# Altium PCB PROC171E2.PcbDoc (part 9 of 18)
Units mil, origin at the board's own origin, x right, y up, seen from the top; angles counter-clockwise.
Board outline 7700 x 2300 mil, 6 copper layers (Top Layer, GND 1, SIG 1, SIG 2, GND 2, Bottom Layer), stack 61.062 mil thick; 937 components, 687 nets, 11931 pads, 1719 vias.
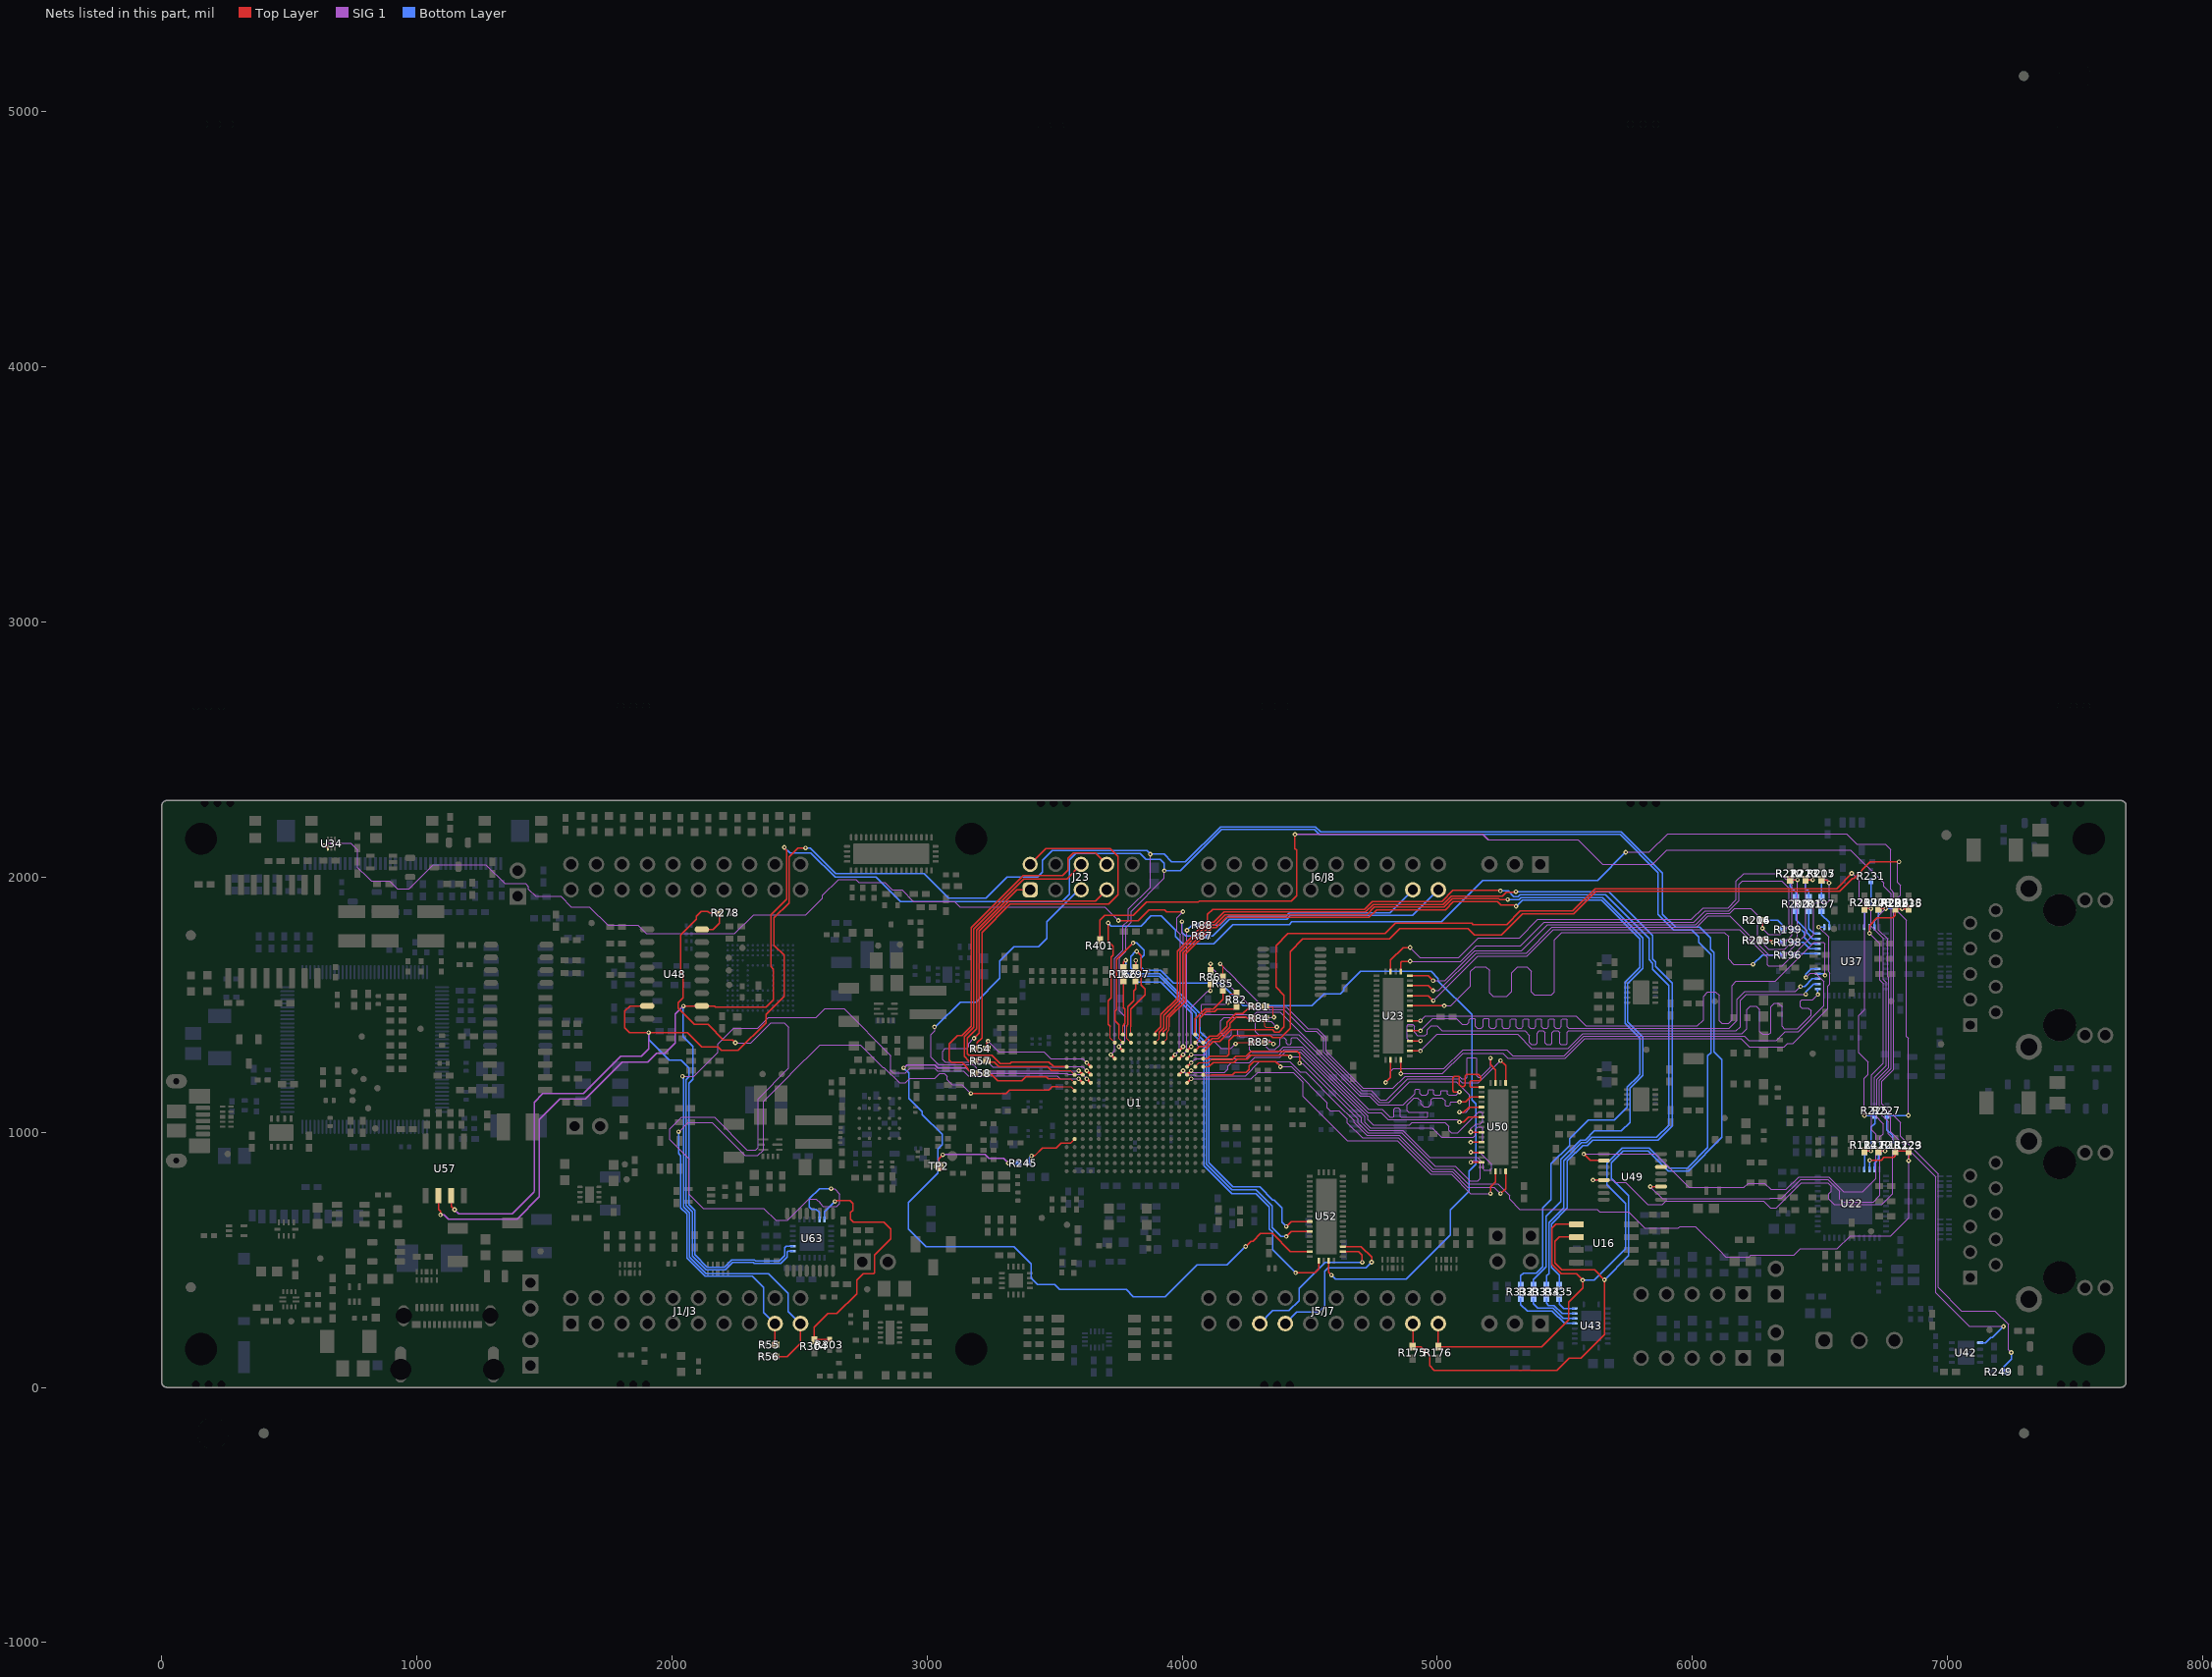
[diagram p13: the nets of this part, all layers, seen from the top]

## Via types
v1: diameter 18, hole 8, Top Layer to Bottom Layer, tented both sides, 1588 vias
v2: diameter 19.68, hole 7.87, Top Layer to Bottom Layer, tented both sides, 104 vias
v3: diameter 19.68, hole 7.87, Top Layer to Bottom Layer, 24 vias
v4: diameter 18, hole 8, Top Layer to Bottom Layer, 3 vias

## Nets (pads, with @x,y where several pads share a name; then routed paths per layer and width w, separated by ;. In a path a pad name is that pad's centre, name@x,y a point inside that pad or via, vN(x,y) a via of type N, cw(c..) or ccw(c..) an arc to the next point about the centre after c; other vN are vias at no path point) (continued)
AM263P_EQEP2_A: R332.1 U1.B13 | length 4022.5
  Top Layer w4: U1.B13@3925.09,1351.3 3940.83,1367.05 3940.83,1392.36 3949.66,1401.19 3949.66,1414.29
  Top Layer w5.3: 3949.66,1414.29 3949.66,1449.05 4013.1,1512.49 4013.1,1697.42 4117.13,1801.45 4132.6,1801.45 4173.13,1841.98 4732.22,1841.98 4762.54,1872.29 5031.26,1872.29 5063.8,1904.82 5236.7,1904.82 5250.28,1891.24 5300.05,1891.24 5305.32,1885.97 v1(5308.76,1885.97)
  Bottom Layer w5.3: v1(5308.76,1885.97) 5310.2,1885.97 5333.66,1909.42 5643.13,1909.42 5794.52,1758.03 5794.52,1646.1 5736.23,1587.8 5736.23,1427.78 5794.52,1369.49 5794.52,1226.91 5787.86,1220.25 5787.86,1219.97 5744.4,1176.5 5744.4,1097.83 5694.68,1048.11 5591.4,1048.11 5518.6,975.3 5518.6,948.55 5445.79,875.74 5445.79,735.68 5413.06,702.96 5413.06,473.21 5387.95,448.1 5338.15,448.1 5327.45,437.4 R332.1@5327.45,397.13
AM263P_EQEP2_A_R: R332.2 U43.6 | length 266.9
  Bottom Layer w5.3: R332.2@5327.45,349.89 5327.45,325.16 5352.6,300 5449.54,300 5499.07,250.47 U43.6@5538.7,250.47
AM263P_EQEP2_B: R333.1 U1.A13 | length 3975.7
  Top Layer w5.3: U1.A13@3925.09,1382.8 3926.32,1384.03 3926.32,1393.32 3938.37,1405.37 3938.37,1414.29 3938.37,1452.75 4002.5,1516.88 4002.5,1701.81 4112.74,1812.05 4128.21,1812.05 4168.74,1852.58 4723.68,1852.58 4754,1882.89 5026.87,1882.89 5059.41,1915.42 5241.09,1915.42 5244.49,1912.02 v1(5276.04,1912.02)
  Bottom Layer w5.3: v1(5276.04,1912.02) 5321.26,1912.02 5329.27,1920.02 5647.52,1920.02 5805.12,1762.42 5805.12,1641.71 5746.83,1583.41 5746.83,1432.17 5805.12,1373.88 5805.12,1222.24 5755,1172.11 5755,1038.76 5721.24,1005 5614.98,1005 5579.67,969.69 5561.6,969.69 5484.84,892.93 5484.84,727.99 5426.85,670 5426.85,472.01 5377.45,422.6 R333.1@5377.45,397.13
AM263P_EQEP2_B_R: R333.2 U43.7 | length 207.4
  Bottom Layer w5.3: R333.2@5377.45,349.89 5377.45,327.55 5394.4,310.6 5453.93,310.6 5494.38,270.15 U43.7@5538.7,270.15
AM263P_EQEP2_INDEX: R334.1 U1.A12 | length 4162.8
  Top Layer w5.3: U1.A12@3893.59,1382.8 3895.28,1384.49 3895.28,1392.88 3916.69,1414.29 3916.69,1461.05 3980.57,1524.93 3980.57,1709.86 4099.4,1828.69 4099.4,1853.45 4119.73,1873.78 4714.38,1873.78 4744.7,1904.09 5018.09,1904.09 5061.62,1947.62 5246.01,1947.62 v1(5247.69,1945.94)
  Bottom Layer w5.3: v1(5247.69,1945.94) 5277.72,1945.94 5300.15,1923.52 5317.77,1923.52 5324.87,1930.62 5659.38,1930.62 5830,1760 5830,1676.8 5844.52,1662.28 5844.52,1637.83 5907.5,1574.85 5907.5,1027.26 5860.24,980 5604.97,980 5584.06,959.09 5565.99,959.09 5495.44,888.54 5495.44,702.96 5437.45,644.97 5437.45,446.35 5428.06,436.97 R334.1@5428.06,397.13
AM263P_EQEP2_INDEX_R: R334.2 U43.8 | length 147.2
  Bottom Layer w5.3: R334.2@5428.06,349.89 5428.06,330 5436.86,321.2 5458.32,321.2 5489.68,289.84 U43.8@5538.7,289.84
AM263P_EQEP2_STROBE: R335.1 U1.B12 | length 4191.5
  Top Layer w4: U1.B12@3893.59,1351.3 3910,1367.71 3910,1385
  Top Layer w5.3: 3910,1385 3910,1391.99 3927.64,1409.63 3927.64,1414.29 3927.64,1457.01 3991.29,1520.66 3991.29,1705.59 4108.35,1822.65 4123.82,1822.65 4164.35,1863.18 4718.97,1863.18 4749.28,1893.49 5022.48,1893.49 5055.01,1926.02 5255.38,1926.02 5270.45,1941.1 5306.3,1941.1 v1(5308.24,1943.04)
  Bottom Layer w5.3: v1(5308.24,1943.04) 5671.96,1943.04 5843.5,1771.5 5843.5,1679.5 5855.48,1667.52 5855.48,1650.65 5921,1585.12 5921,1025.46 5865,969.46 5865,969.4 5609.36,969.4 5588.45,948.49 5570.38,948.49 5510,888.11 5510,702.53 5448.05,640.58 5448.05,469.67 5478.01,439.71 R335.1@5478.01,397.13
AM263P_EQEP2_STROBE_R: R335.2 U43.9 | length 91.1
  Bottom Layer w5.3: R335.2@5478.01,349.89 5478.01,326.51 5495,309.52 U43.9@5538.7,309.52
AM263P_EXT_REFCLK0: R245.2 TP2.1 | length 365.9
  Top Layer w5.3: TP2.1@3046.89,866.63 3046.89,896.68 v1(3061.63,911.42) ; v1(3318.54,878.86) v1@3320.15,880.47
  SIG 1 w5.3: v1(3061.63,911.42) 3062.87,912.67 3227.95,912.67 3243.11,897.5 3299.9,897.5 v1(3318.54,878.86)
  Bottom Layer w5.3: v1@3317.75,877.43 3356.3,877.43 R245.2@3358.26,879.39
AM263P_EXT_REFCLK0_R: R245.1 U1.P2 | length 230.8
  Top Layer w6: v1@3409.5,905.14 3412.6,908.24 3422.07,908.24 3451.8,937.97 3505.94,937.97 3515.64,947.66 3525.05,957.07 3563.22,957.07 3578.63,972.48 U1.P2@3578.63,973.35
  Bottom Layer w6: R245.1@3397.63,879.39 3399.6,881.36 3399.6,897.62 v1(3409.42,907.44)
AM263P_FSIRX1_CLK: J23.1 U1.E1 | length 1191.5
  Top Layer w5.3: J23.1@3404.17,1950 3351.31,1950 3193.88,1792.57 3193.88,1406.29 3157.31,1369.72 3157.31,1308.22 3164.4,1301.12 3254.65,1301.12 3287.22,1268.54 3324.45,1268.54 3330.96,1275.05 3477.96,1275.05 3496.2,1256.81 U1.E1@3547.13,1256.81
AM263P_FSIRX1_DATA0: J23.5 U1.F3 | length 1625.3
  Top Layer w10: v1(3594.38,1241.06) U1.F3@3610.13,1225.32
  SIG 1 w4: 3515.64,1241.06 v1(3594.38,1241.06)
  SIG 1 w4.75: v1(3028.75,1413.07) 3030.54,1411.28 3030.54,1397.07 3015.66,1382.19 3015.66,1293.34 3044.56,1264.44 3181.29,1264.44 3204.67,1241.06 3515.64,1241.06
  Bottom Layer w5.3: v1(3028.75,1413.07) 3032.18,1413.07 3036.81,1417.7 3037.49,1417.7 3130.32,1510.52 3192.55,1510.52 3285.17,1603.14 3285.17,1670.79 3340.49,1726.11 3436.11,1726.11 3470,1760 3470,1825.78 3587.73,1943.5 3597.67,1943.5 J23.5@3604.17,1950
AM263P_FSIRX1_DATA1: J23.7 U1.F4 | length 1786.4
  Top Layer w5.3: v1(3184.29,1368.47) 3204.48,1388.67 3204.48,1788.18 3321.8,1905.5 3659.67,1905.5 J23.7@3704.17,1950
  Top Layer w10: v1(3625.87,1241.06) U1.F4@3641.62,1225.32
  SIG 1 w4: 3538.18,1257.18 3604.95,1257.18 3605.32,1256.81 3610.13,1256.81 v1(3625.87,1241.06)
  SIG 1 w4.75: v1(3184.29,1368.47) 3183.67,1368.47 3163.43,1348.23 3163.43,1336.01 3155.32,1327.89 3071.12,1327.89 3060.93,1317.71 3060.93,1284.83 3071.27,1274.49 3238,1274.49 3257.49,1255 3515.64,1255 3536,1255 3538.18,1257.18
AM263P_FSITX1_CLK: J23.2 R54.1 | length 1595.6
  Top Layer w5.3: R54.1@3186.06,1327.26 3187.98,1327.26 3197.14,1336.42 3197.14,1351.52 3215.08,1369.46 3215.08,1783.79 3325.78,1894.49 3711.88,1894.49 3748.22,1930.82 3748.22,2080.28 3717,2111.5 3465.67,2111.5 J23.2@3404.17,2050
AM263P_FSITX1_CLK_R: R54.2 U1.E4 | length 476.6
  Top Layer w5.3: R54.2@3233.31,1327.26 3233.31,1347.96 3239.25,1353.91 v1(3239.25,1357.34)
  Top Layer w10: v1(3625.87,1272.56) U1.E4@3641.62,1256.81
  SIG 1 w4: 3516.64,1288.5 3609.93,1288.5 v1(3625.87,1272.56)
  SIG 1 w4.75: v1(3239.25,1357.34) 3281.1,1315.5 3458.5,1315.5 3485.5,1288.5 3516.64,1288.5
AM263P_FSITX1_DATA0: J23.6 R57.1 | length 1087.5
  Top Layer w5.3: R57.1@3186.06,1279.26 3164.45,1279.26 3146.71,1297 3146.71,1368.05 3146.71,1374.11 3183.28,1410.68 3183.28,1796.96 3379.82,1993.5 3547.67,1993.5 J23.6@3604.17,2050
AM263P_FSITX1_DATA0_R: R57.2 U1.F2 | length 369.5
  Top Layer w4: 3515.64,1242.94 3561.01,1242.94 U1.F2@3578.63,1225.32
  Top Layer w5.3: R57.2@3229.37,1274.26 3263.46,1274.26 3280.45,1257.28 3472.21,1257.28 3486.55,1242.94 3515.64,1242.94
AM263P_FSITX1_DATA1: J23.8 R58.1 | length 1385
  Top Layer w5.3: R58.1@3186.06,1231.26 3176.9,1240.42 3168.14,1240.42 3149.66,1258.9 3149.66,1261.26 3137.85,1273.07 3096.41,1273.07 3086.08,1283.4 3086.08,1345.64 3119.1,1378.65 3136.26,1378.65 3172.68,1415.07 3172.68,1801.35 3377.83,2006.5 3532,2006.5 3553,2027.5 3553,2074 3573,2094 3660.17,2094 J23.8@3704.17,2050
AM263P_FSITX1_DATA1_R: R58.2 U1.G2 | length 375.5
  Top Layer w4: 3515.64,1209.57 3562.88,1209.57 U1.G2@3578.63,1193.82
  Top Layer w5.3: R58.2@3229.37,1231.26 R58.2@3231.34,1229.29 ; R58.2@3233.31,1231.26 3239.8,1224.77 3253.9,1224.77 3276.19,1202.48 3372.36,1202.48 3386.66,1216.78 3468.18,1216.78 3475.39,1209.57 3515.64,1209.57
AM263P_I2C1_SCL: J5/J7.49 R175.1 U1.D7 U16.6 U48.15 U57.3 U63.19 | length 12800.5
  Top Layer w5.3: U57.3@1134.51,751.17 1134.51,709.57 v1(1147.56,696.52) ; U48.15@1902.72,1495 1836.12,1495 1815.31,1474.19 1815.31,1409.36 1834.1,1390.57 v1(1908.57,1390.57) 2061.37,1390.57 2116.89,1335.05 2180.06,1335.05 2194.47,1320.63 2259.71,1320.63 2368.82,1429.75 2368.82,1461.98 2439.32,1532.48 2439.32,1694.13 2400.25,1733.2 2400.25,1840.08 2459.36,1899.19 2459.36,2078.89 2494.29,2113.81 2523.18,2113.81 v1(2523.43,2114.06) ; J5/J7.49@4904.17,250 4904.17,160.51 R175.1@4903.31,159.65 4935.35,159.65 4970,125 4970,85 4988.58,66.42 5469.31,66.42 5517.89,115 5563.27,115 5655,206.73 v1(5655,421.38) 5616.38,460 5488.71,460 5460.6,488.11 5460.6,571.98 5477.76,589.14 U16.6@5545.51,589.14
  Top Layer w10: v1(3720.36,1304.06) U1.D7@3736.11,1288.31
  SIG 1 w4: v1(3720.36,1304.06) 3735.36,1319.06 3735.36,1414.29
  SIG 1 w4.75: 3735.36,1414.29 3735.36,1681.04 3768.42,1714.1 3768.42,1809.46 3788.96,1830 3788.96,1874.36 3875.05,1960.45 v1(3875.05,2090.05)
  SIG 1 w5.3: v1(1147.56,696.52) 1164.08,680 1374.68,680 1459.24,764.55 1459.65,771.37 1459.65,1117.7 1493.24,1151.3 1652.8,1151.3 1800.19,1298.68 1878.66,1298.68 1880.85,1298.68 1908.57,1326.4 v1(1908.57,1390.57)
  Bottom Layer w5.3: v1(1908.57,1390.57) 1908.57,1364.17 1990.18,1282.56 2036.19,1282.56 2066.43,1252.31 2066.43,1216.29 2055.87,1205.73 2055.87,712.1 2079.4,688.57 2079.4,515.53 2134.33,460.6 2210.09,460.6 2238.88,489.39 2319.16,489.39 2323.32,485.22 2426.48,485.22 2451.91,510.65 2451.91,529.97 2456.2,534.26 U63.19@2474.16,534.26 ; v1(2523.43,2114.06) 2525.03,2113.81 2542.42,2113.81 2641.86,2014.38 2988.14,2014.38 3085.39,1917.13 3231.37,1917.13 3314.22,1999.98 3433.73,1999.98 3452.63,2018.87 3452.63,2064.92 3491.48,2103.78 3861.33,2103.78 v1(3875.05,2090.05) 3928.67,2090.05 3958.8,2059.93 4012.43,2059.93 4149.82,2197.31 4522.96,2197.31 4542.87,2177.41 5720.79,2177.41 5882.72,2015.49 5882.72,1854.22 5933.8,1803.13 6029.61,1803.13 6070.97,1761.78 6070.97,1716.79 6083.8,1703.95 6083.8,1316.2 6115.71,1284.29 6115.71,979.72 5984.47,848.48 5905.04,848.48 5827.42,926.1 5728.23,926.1 5682.27,880.14 5682.27,819.31 5749.4,752.17 5749.4,515.78 v1(5655,421.38)
AM263P_I2C1_SDA: J5/J7.50 R176.1 U1.C8 U16.5 U48.2 U57.2 U63.20 | length 12243.2
  Top Layer w5.3: U57.2@1084.51,751.17 1084.51,698.33 1092.5,690.34 v1(1092.5,675.88) ; v1(2044.99,1494.52) 2045.03,1494.57 2116.85,1494.57 U48.2@2117.28,1495 2166.01,1495 2170.45,1490.56 2231.47,1490.56 2369.41,1490.56 2397.81,1518.96 2397.81,1638.97 2387.33,1649.45 2387.33,1851.36 2448.76,1912.79 2448.76,2104.87 2440.58,2113.06 v1(2440.58,2116.49) ; J5/J7.50@5004.17,250 R176.1@5004.17,159.65 5409.65,159.65 5515,265 5515,334.61 5570,389.61 v1(5570,420) 5545,445 5486.14,445 5450,481.14 5450,625 5464.14,639.14 U16.5@5545.51,639.14
  Top Layer w10: v1(3751.86,1335.55) U1.C8@3767.61,1319.8
  SIG 1 w4: v1(3751.86,1335.55) 3775.62,1359.32 3775.62,1425.57
  SIG 1 w4.75: 3775.62,1425.57 3775.62,1453.13 3753.75,1475 3753.75,1685.22 3778.47,1709.93 3778.47,1802.62 3800,1824.15 3800,1866.12 3930,1996.12 v1(3930,2024.75)
  SIG 1 w5.3: v1(1092.5,675.88) 1106.96,675.88 1123.49,659.35 1392.53,659.35 1480.31,747.13 1480.31,1050.57 1560.38,1130.65 1661.35,1130.65 1805.82,1275.11 1905,1275.11 1922.87,1292.98 1940.66,1310.45 1973.07,1310.45 2012.52,1349.9 2012.52,1462.69 2044.35,1494.52 v1(2044.99,1494.52)
  Bottom Layer w5.3: v1(2044.99,1494.52) 2043.96,1493.49 2043.96,1374.31 2082.6,1335.67 2082.6,1207.77 2066.47,1191.65 2066.47,716.49 2090,692.97 2090,519.92 2138.72,471.2 2205.7,471.2 2234.49,499.99 2323.55,499.99 2327.71,495.82 2420.18,495.82 2441.31,516.95 2441.31,547.87 2447.39,553.95 U63.20@2474.16,553.95 ; v1(2440.58,2116.49) 2460.98,2096.09 2462.53,2094.54 2545.02,2094.54 2546.57,2092.98 2639.6,1999.96 2800.02,1999.96 2895.45,1904.53 3528.85,1904.53 3558.06,1933.74 3558.06,2068.59 3582.65,2093.18 3835.03,2093.18 3857.68,2070.53 3913.88,2070.53 3930,2054.41 v1(3930,2024.75) 3993.14,2024.75 4155.1,2186.71 4518.31,2186.71 4538.21,2166.81 5716.4,2166.81 5865,2018.21 5865,1854.37 5926.84,1792.53 5998.02,1792.53 6025,1765.56 6025,1744.48 6073.2,1696.28 6073.2,1311.78 6060.48,1299.05 6060.48,939.48 5980.08,859.08 5909.44,859.08 5830.92,937.6 5724.74,937.6 5665.6,878.46 5665.6,793.26 5738.8,720.06 5738.8,543.9 5614.9,420 v1(5570,420)
AM263P_I2C3_SCL: J1/J3.9 R55.1 U1.H2 | length 3144.2
  Top Layer w4: 3515.64,1177.69 3563.27,1177.69 U1.H2@3578.63,1162.32
  Top Layer w5.3: R55.1@2404.17,170 J1/J3.9@2404.17,250 ; v1(3171.61,1152.13) 3191.21,1151.54 3309.84,1151.54 3322.76,1164.47 3477.91,1164.47 3491.13,1177.69 3515.64,1177.69
  SIG 1 w4.75: v1(2025.75,1002.09) 2028.24,1002.09 2063.81,1037.66 2157.87,1037.66 2286.49,909.03 2336.73,909.03 2358.9,931.2 2358.9,1120.98 2465.35,1227.43 2465.35,1227.82 2580.45,1342.92 2737.8,1342.92 2826.21,1254.51 2831.08,1254.51 2892.09,1193.5 2915.59,1193.5 2932.73,1210.64 3030.52,1210.64 3050.04,1230.16 3068.18,1230.16 3079.45,1218.89 3079.45,1205.56 3098.1,1186.91 3136.83,1186.91 v1(3171.61,1152.13)
  Bottom Layer w5.3: v1(2025.75,1002.09) 2025.75,917.01 2034.67,908.09 2034.67,703.32 2058.2,679.79 2058.2,506.75 2129.9,435.06 2315.8,435.06 2360,390.85 2360,294.17 J1/J3.9@2404.17,250
AM263P_I2C3_SDA: J1/J3.10 R56.1 U1.G3 | length 3368.7
  Top Layer w5.3: R56.1@2404.59,121 2452.33,121 2504.17,172.84 J1/J3.10@2504.17,250
  Top Layer w10: v1(3594.38,1209.57) U1.G3@3610.13,1193.82
  SIG 1 w4.75: v1(2041.52,1218.99) 2085.81,1218.99 2180.61,1313.79 2180.61,1345.43 2242.1,1406.92 2336.03,1406.92 2379.04,1449.94 2565.75,1449.94 2599.52,1483.71 2674.26,1483.71 2857.96,1300.01 2857.96,1241.85 2867.05,1232.76 2905.22,1232.76 2916.06,1232.74 2927.35,1244.03 2934.89,1251.58 3028.21,1251.58 3039.58,1240.21 3142.02,1240.21 3161.82,1220.41 3509.8,1220.41 3520.64,1209.57 v1(3594.38,1209.57)
  Bottom Layer w5.3: v1(2041.52,1218.99) 2043.95,1216.56 2043.95,1210.86 2045.27,1209.53 2045.27,707.71 2068.8,684.18 2068.8,511.14 2134.29,445.66 2379.01,445.66 2456.13,368.54 2456.13,298.04 J1/J3.10@2504.17,250
AM263P_ICSSM_MII0_COL: R207.1 R219.2 R231.2 U37.45 U49.11 | length 2477.8
  Top Layer w5.3: v1(5835,786.84) U49.11@5877.2,786.84 ; R207.1@6674.39,1876.46 v1(6700,1876.46)
  SIG 1 w4.75: v1(5835,786.84) 5881.84,740 6304.59,740 6305.65,741.06 6350.52,741.06 6424.46,815 6531.49,815 6578.11,768.37 6578.11,738.69 6589.88,726.92 6710,726.92 6735.75,752.67 6735.75,981.83 6748.64,994.71 6748.64,1033.27 6713.34,1068.57 6713.34,1215.64 6759.37,1261.68 6759.37,1322.67 6759.37,1586.7 6748.64,1597.44 6748.64,1759.67 6700,1808.31 v1(6700,1876.46)
  Bottom Layer w5.3: U37.45@6674.39,1803.9 6674.52,1804.03 6674.52,1876.32 R219.2@6674.39,1876.46 v1(6700,1876.46) R231.2@6700,1985
AM263P_ICSSM_MII0_CRS: U49.14
AM263P_ICSSM_MII0_RXCLK: R196.1 U23.32 | length 2179.7
  Top Layer w5.3: U23.32@4892.17,1495.87 v1(5026.97,1495.87)
  SIG 1 w4.75: v1(5026.97,1495.87) 5052.52,1495.87 5130,1573.35 5130,1630 5148.88,1648.88 5190,1648.88 5205,1633.88 5205,1547.01 5218.7,1533.31 5272.43,1533.31 5290.93,1551.81 5290.93,1625.68 5314.12,1648.88 5351.12,1648.88 5368.7,1631.3 5368.7,1550.78 5381.13,1538.35 5447.26,1538.35 5458.38,1549.47 5458.38,1753.76 5488.38,1783.75 6124.51,1783.75 6141.53,1766.73 6141.53,1678.12 6161.56,1658.09 v1(6237.52,1658.09)
  Bottom Layer w5.3: v1(6237.52,1658.09) 6274.47,1695.04 R196.1@6351.89,1695.04
AM263P_ICSSM_MII0_RXCLK_R: R196.2 U37.32 | length 94.1
  Bottom Layer w5.3: R196.2@6399.14,1695.04 6403.66,1699.57 U37.32@6491.32,1699.57
AM263P_ICSSM_MII0_RXD0: R198.1 R203.1 R215.2 U23.41 | length 2256.6
  Top Layer w5.3: U23.41@4817.36,1629.73 4817.36,1674.62 4866.61,1723.86 v1(4893.56,1723.86) ; R203.1@6275,1752.65 6307.35,1752.65 v1(6315,1745)
  SIG 1 w4.75: v1(4893.56,1723.86) 4932.42,1685 5083.11,1685 5160.35,1762.24 5322.96,1762.24 5394.72,1834 5996.48,1834 6042.48,1880 6140,1880 6172.02,1912.02 6172.02,1984.09 6202.08,2014.15 6344.69,2014.15 6390,1968.84 6390,1773.91 6361.09,1745 v1(6315,1745)
  Bottom Layer w5.3: R215.2@6274.92,1752.65 6305.55,1752.65 6313.2,1745 v1(6315,1745) v1(6315,1745) R198.1@6351.89,1745.04
AM263P_ICSSM_MII0_RXD0_R: R198.2 U37.33 | length 102.9
  Bottom Layer w5.3: R198.2@6399.14,1745.04 6434.21,1745.04 6460,1719.25 U37.33@6491.32,1719.25
AM263P_ICSSM_MII0_RXD1: R199.1 R204.1 R216.2 U23.39 | length 2182.3
  Top Layer w5.3: U23.39@4856.73,1629.73 4856.73,1664.99 4861.74,1670 v1(4893.56,1670) ; v1(6274.92,1798.96) 6275,1799.04 R204.1@6275,1830.96
  SIG 1 w4.75: v1(4893.56,1670) 5092.52,1670 5153.02,1730.5 5326.09,1730.5 5419.54,1823.95 6004.95,1823.95 6049.09,1868.09 6142.3,1868.09 6182.07,1907.86 6182.07,1970.68 6196.35,1984.95 6350.79,1984.95 6379.95,1955.79 6379.95,1809.66 6345.29,1775 6298.88,1775 v1(6274.92,1798.96)
  Bottom Layer w5.3: v1(6274.92,1798.96) 6275,1799.04 R216.2@6275,1830.96 6275.11,1830.85 6335,1830.85 6351.89,1813.96 R199.1@6351.89,1795.04
AM263P_ICSSM_MII0_RXD1_R: R199.2 U37.34 | length 126.8
  Bottom Layer w5.3: R199.2@6399.14,1795.04 6399.18,1795 6425.16,1795 6438.01,1782.15 6438.01,1762.74 6461.81,1738.94 U37.34@6491.32,1738.94
AM263P_ICSSM_MII0_RXD2: R200.1 R210.1 R222.2 U23.38 | length 2143.2
  Top Layer w5.3: U23.38@4892.17,1613.98 4964.13,1613.98 v1(4983.82,1594.29) ; R210.1@6383.01,1989.35 6411.65,1989.35 v1(6411.73,1989.27)
  SIG 1 w4.75: v1(4983.82,1594.29) 5031.03,1594.29 5148.36,1711.62 5329.69,1711.62 5431.97,1813.9 6013.95,1813.9 6058.09,1858.04 6146.47,1858.04 6165.12,1876.69 6228.31,1876.69 6255.67,1849.33 6255.67,1760.83 6298.88,1717.62 6362.62,1717.62 6411.73,1766.73 v1(6411.73,1989.27)
  Bottom Layer w5.3: R200.1@6406.28,1918.62 6406.28,1941.33 6383.01,1964.61 R222.2@6383.01,1989.35 6411.65,1989.35 v1(6411.73,1989.27)
AM263P_ICSSM_MII0_RXD2_R: R200.2 U37.35 | length 159.3
  Bottom Layer w5.3: R200.2@6406.28,1871.38 6406.28,1833.72 6448.61,1791.39 6448.61,1781.98 6471.97,1758.62 U37.35@6491.32,1758.62
AM263P_ICSSM_MII0_RXD3: R201.1 R211.1 R223.2 U23.36 | length 2185.7
  Top Layer w5.3: U23.36@4892.17,1574.61 4964.13,1574.61 v1(4983.82,1554.92) ; R211.1@6443.01,1989.35 v1(6471.73,1989.27) v1(6471.73,1989.27)
  SIG 1 w4.75: v1(4983.82,1554.92) 5005.87,1554.92 5152.52,1701.57 5331.99,1701.57 ccw(c5331.99,1706.32) 5333.16,1701.72 5335.42,1702.29 cw(c5336.59,1697.69) 5336.54,1702.44 5349.02,1702.53 5450.34,1803.85 6018.14,1803.85 6062.28,1847.99 6147.02,1847.99 6300.01,1695 6364.04,1695 6444.47,1775.43 6444.47,1999.47 6455,2010 6467.22,2010 6471.73,2005.49 v1(6471.73,1989.27)
  Bottom Layer w5.3: R201.1@6456.28,1918.62 6456.28,1943.72 6443.01,1956.99 R223.2@6443.01,1989.35 v1(6471.73,1989.27) v1(6471.73,1989.27)
AM263P_ICSSM_MII0_RXD3_R: R201.2 U37.36 | length 116.2
  Bottom Layer w5.3: R201.2@6456.28,1871.38 6456.28,1798.71 6476.68,1778.31 U37.36@6491.32,1778.31
AM263P_ICSSM_MII0_RXDV: R197.1 R205.1 R217.2 U23.34 | length 2228.3
  Top Layer w5.3: U23.34@4892.17,1535.24 4964.74,1535.24 v1(4984.43,1515.55) ; R205.1@6506.28,1989.43 6526.56,1989.43 6536.12,1979.87 v1(6536.12,1977.35)
  SIG 1 w4.75: v1(4984.43,1515.55) 5159.93,1691.06 5351.76,1691.06 5454.5,1793.8 6185.09,1793.8 6294.37,1684.51 6294.37,1656.36 6298.18,1652.56 6352.8,1652.56 6475.75,1775.51 6475.75,1890 6485.75,1900 6528.66,1900 6536.12,1907.46 v1(6536.12,1977.35)
  Bottom Layer w5.3: R197.1@6506.28,1918.62 R217.2@6506.28,1989.43 6526.56,1989.43 6536.12,1979.87 v1(6536.12,1977.35)
AM263P_ICSSM_MII0_RXDV_R: R197.2 U37.38 | length 80
  Bottom Layer w5.3: R197.2@6506.28,1871.38 6506.28,1852.66 6536.59,1822.35 U37.38@6536.59,1803.9
AM263P_ICSSM_MII0_RXER: R206.1 R218.2 R235.2 U37.46 U49.2 | length 2656.3
  Top Layer w5.3: v1(5574.59,914.8) 5600.18,889.2 U49.2@5652.8,889.2 ; v1(6694.59,1779.98) 6694.07,1780.5 6694.07,1810.03 6724.04,1840 6785,1840 6795,1850 6795,1874.79 R206.1@6796.28,1876.06 v1(6822.14,1876.06) R218.2@6848,1876.06
  SIG 1 w4.75: v1(5574.59,914.8) 5854.89,914.8 5986.39,783.3 6203.03,783.3 6219.76,800.03 6282.75,800.03 6307.03,775.75 6367.49,775.75 6416.79,825.05 6535.65,825.05 6593.6,767.1 6667.1,767.1 6719.25,819.25 6719.25,992.92 6703.29,1008.88 6703.29,1224.29 6749.32,1270.33 6749.32,1318.51 6749.32,1582.54 6735.75,1596.11 6735.75,1738.3 6694.59,1779.46 v1(6694.59,1779.98)
  Bottom Layer w5.3: U37.46@6694.07,1803.9 6694.33,1803.64 6694.33,1780.24 v1(6694.59,1779.98) ; v1(6822.14,1876.06) 6822.77,1876.69 R235.2@6848,1876.69
AM263P_ICSSM_MII0_RXLINK: R208.1 R220.2 R233.2 U37.47 U49.5 | length 2771.9
  Top Layer w5.3: v1(5610.59,812.43) U49.5@5652.8,812.43 ; R208.1@6729.39,1876.46 v1(6758,1876.46)
  SIG 1 w4.75: v1(5610.59,812.43) 5689.53,812.43 5697.98,803.98 5737.42,803.98 5824.99,716.41 5881.68,716.41 5895.21,729.95 6278.26,729.95 6305.65,702.56 6329.24,702.56 6427.29,800.6 6531.62,800.6 6544.25,787.97 6544.25,768.34 6534.22,758.31 6534.22,738.69 6556.04,716.87 6741.87,716.87 6785,760 6785,975.92 6766.98,993.94 6766.98,1041.66 6723.39,1085.25 6723.39,1208.39 6769.42,1254.42 6769.42,1326.83 6769.42,1605.75 6765,1610.18 6765,1757.52 6730,1792.52 6730,1848.46 v1(6758,1876.46)
  Bottom Layer w5.3: U37.47@6713.76,1803.9 6713.76,1829.37 6729.39,1845 R220.2@6729.39,1876.46 v1(6758,1876.46) 6794.76,1876.46 R233.2@6795,1876.69
AM263P_ICSSM_MII0_TXCLK: U23.19 U37.29 | length 2240.6
  Top Layer w5.3: v1(4797.68,1195.01) 4817.36,1214.69 U23.19@4817.36,1283.27
  SIG 1 w4.75: v1(4797.68,1195.01) 4816.93,1214.26 4816.93,1237.36 4828.77,1249.2 5026.48,1249.2 5100.59,1323.32 5271.68,1323.32 5295,1300 5497.08,1300 5574.45,1377.37 6203.73,1377.37 6221,1360.1 6329.33,1360.1 6364.23,1395 6414.93,1395 6516.08,1496.16 6516.08,1590.42 6483.53,1622.97 6461.5,1622.97 v1(6445,1606.47)
  Bottom Layer w5.3: v1(6445,1606.47) 6445,1619.87 6465.64,1640.51 U37.29@6491.32,1640.51
AM263P_ICSSM_MII0_TXD0: U23.29 U37.28 | length 2238.6
  Top Layer w5.3: U23.29@4892.17,1436.81 v1(4933.82,1436.81)
  SIG 1 w4.75: v1(4933.82,1436.81) 4953.26,1456.25 5543.75,1456.25 5582.43,1417.57 6020,1417.57 6043.31,1440.89 6043.31,1533.31 6060,1550 6090.94,1550 6104.93,1536.01 6104.93,1437.02 6114.98,1426.97 6141.97,1426.97 6155,1440 6155,1575.32 6172.02,1592.34 6325.23,1592.34 6477.9,1745 6514.23,1745 6520,1739.23 v1(6520,1615)
  Bottom Layer w5.3: U37.28@6491.32,1620.83 6514.17,1620.83 v1(6520,1615)
AM263P_ICSSM_MII0_TXD1: U23.27 U37.27 | length 2238.5
  Top Layer w5.3: U23.27@4892.17,1397.44 v1(4933.82,1397.44)
  SIG 1 w4.75: v1(4933.82,1397.44) 4982.58,1446.2 5073.64,1446.2 5097.17,1422.67 5116.6,1422.67 5125,1431.08 5125,1441.2 5130,1446.2 5145.03,1446.2 5150,1441.23 5150,1415.63 5157.93,1407.7 5171.95,1407.7 5180,1415.76 5180,1441.63 5184.57,1446.2 5200,1446.2 5204.29,1441.91 5204.29,1413.41 5210,1407.7 5225,1407.7 5231.71,1414.41 5231.71,1439.62 5237.09,1445 5250,1445 5255,1440 5255,1412.7 5260,1407.7 5280,1407.7 5286.71,1414.41 5286.71,1439.62 5292.09,1445 5305,1445 5310,1440 5310,1412.7 5315,1407.7 5330,1407.7 5336.71,1414.41 5336.71,1439.62 5342.09,1445 5355,1445 5360,1440 5360,1412.7 5365,1407.7 5380,1407.7 5386.71,1414.41 5386.71,1439.62 5392.09,1445 5405,1445 5410,1440 5410,1412.7 5415,1407.7 5430,1407.7 5436.71,1414.41 5436.71,1439.62 5442.09,1445 5455,1445 5460,1440 5460,1412.7 5465,1407.7 5480,1407.7 5486.71,1414.41 5486.71,1439.62 5492.09,1445 5505,1445 5510,1440 5510,1412.7 5515.18,1407.52 6145,1407.52 6175,1437.52 6175,1520.85 6206.45,1552.3 6404.57,1552.3 v1(6423.51,1571.24)
  Bottom Layer w5.3: v1(6423.51,1571.24) 6439.75,1571.24 6469.65,1601.14 U37.27@6491.32,1601.14
AM263P_ICSSM_MII0_TXD2: U23.25 U37.26 | length 2238.4
  Top Layer w5.3: U23.25@4892.17,1358.07 v1(4933.82,1358.07)
  SIG 1 w4.75: v1(4933.82,1358.07) 4890.94,1358.07 4881.77,1367.25 4881.77,1417.84 4886.61,1422.67 4903.59,1422.67 4910,1416.26 4910,1391.44 4923.24,1378.19 4952.19,1378.19 4961,1387 4961,1401.85 4975.85,1416.69 4999.73,1416.69 5018.95,1397.47 5343.6,1397.47 5361.5,1379.57 5361.5,1351.08 5369.16,1343.42 5385.21,1343.42 5391.78,1349.99 5391.78,1389.25 5400,1397.47 5415,1397.47 5422.49,1389.98 5422.49,1350.49 5428.06,1344.92 5445.48,1344.92 5450,1349.43 5450,1390 5457.47,1397.47 5472.53,1397.47 5480,1390 5480,1348.38 5484.96,1343.42 5506.27,1343.42 5510,1347.15 5510,1392.47 5515,1397.47 6171.47,1397.47 6187.84,1413.84 6187.84,1517.25 6211.44,1540.85 v1(6444.47,1540.85)
  Bottom Layer w5.3: v1(6444.47,1540.85) 6444.47,1550.71 6475.21,1581.46 U37.26@6491.32,1581.46
AM263P_ICSSM_MII0_TXD3: U23.23 U37.25 | length 2240.1
  Top Layer w5.3: U23.23@4892.17,1318.7 v1(4933.82,1318.7)
  SIG 1 w4.75: v1(4933.82,1318.7) 4999.46,1384.35 5314.02,1384.35 5369,1329.37 5512.23,1329.37 5570.29,1387.42 6195,1387.42 6213.36,1405.78 6213.36,1481.49 6226.22,1494.36 6250.2,1494.36 6263.7,1480.85 6263.7,1394.54 6274.46,1383.78 6299.87,1383.78 6307.32,1391.23 6307.32,1492.72 6320.6,1506 6336.86,1506 6351.36,1491.5 6351.36,1415.04 6360.4,1406 6411.71,1406 6465,1459.29 6465,1476.21 6454.84,1486.37 6428.68,1486.37 6422.79,1492.26 6422.79,1514.18 6428.61,1520 6472.17,1520 v1(6492.17,1540)
  Bottom Layer w5.3: U37.25@6491.32,1561.77 6491.32,1540.85 v1(6492.17,1540)
AM263P_ICSSM_MII0_TXEN: U23.21 U37.37 | length 2239.7
  Top Layer w5.3: U23.21@4856.73,1283.27 4856.73,1230.33 v1(4857.11,1229.96)
  SIG 1 w4.75: v1(4857.11,1229.96) 4857.15,1230 5021.49,1230 5101.48,1309.99 5257.38,1309.99 5277.42,1289.95 5501.24,1289.95 5578.61,1367.32 6190.85,1367.32 6223.21,1334.96 6360.2,1334.96 6373.06,1347.82 6395.09,1347.82 6531.62,1484.35 6531.62,1572.37 6539.25,1580 6539.25,1622.97 6534.22,1628 6534.22,1764.68 v1(6495,1803.9)
  Bottom Layer w5.3: v1(6495,1803.9) U37.37@6516.91,1803.9
AM263P_ICSSM_MII1_COL: R112.1 R124.2 R225.2 U1.C18 U22.45 | length 4383.9
  Top Layer w5.3: U1.C18@4082.57,1319.8 4086.6,1319.8 4122.5,1355.7 4146.29,1355.7 4191.74,1401.15 4354.6,1401.15 4362.85,1392.9 4379.03,1392.9 4399.89,1413.76 4399.89,1537.42 4367.66,1569.64 4367.66,1731.16 4414.88,1778.38 4794.45,1778.38 4835.37,1819.29 5135.52,1819.29 5140.61,1814.2 5272.38,1814.2 5325.08,1866.9 5530.18,1866.9 5618.28,1955 6564.92,1955 v1(6624.77,2014.85) ; R112.1@6674.39,926.46 v1(6700,926.46)
  SIG 1 w4.75: v1(6624.77,2014.85) 6655.14,1984.49 6655.14,1912.02 6675.34,1891.82 6675.34,1481.02 6652.14,1457.82 6652.14,1311.31 6689.32,1274.13 6689.32,1225.94 6674.39,1211 v1(6674.39,1065)
  Bottom Layer w5.3: U22.45@6674.39,853.9 6674.52,854.03 6674.52,926.32 R124.2@6674.39,926.46 v1(6700,926.46) 6700,1020 6715,1035 R225.2@6715,1064.94 6674.45,1064.94 v1(6674.39,1065)
AM263P_ICSSM_MII1_RXCLK: U1.E16 U50.31 | length 1530.3
  Top Layer w5.3: v1(5131.16,1000.35) U50.31@5173.43,1000.35
  Top Layer w10: U1.E16@4019.57,1256.81 v1(4035.32,1272.56)
  SIG 1 w4: v1(4035.32,1272.56) 4051.82,1289.06 4114.06,1289.06
  SIG 1 w4.75: 4114.06,1289.06 4250.66,1289.06 4265.61,1304 4379.88,1304 4400.29,1324.4 4466.88,1324.4 4728.5,1062.79 4728.5,1048.88 4749.39,1027.99 4891.44,1027.99 4901.66,1038.21 5029.44,1038.21 5045,1022.66 5045,1007.89 5055.05,997.84 5080.12,997.84 5163.56,1081.29 5170.68,1081.29 5177.73,1074.24 5177.73,1041.58 5168.72,1032.57 5150.46,1032.57 5131.16,1013.27 v1(5131.16,1000.35)
AM263P_ICSSM_MII1_RXD0: U1.F18 U50.42 | length 1527.9
  Top Layer w4: U1.F18@4082.57,1225.32 4113.77,1225.32 4114.06,1225.03
  Top Layer w5.3: 4114.06,1225.03 4115.16,1223.93 4196.2,1223.93 4206.8,1234.53 4250.64,1234.53 4262.08,1245.97 4262.08,1260.07 4279.71,1277.7 4366.78,1277.7 4384.99,1259.48 v1(4384.99,1256.82) ; v1(5248.23,759.55) 5267.91,779.23 U50.42@5267.91,846.81
  SIG 1 w4.75: v1(4384.99,1256.82) 4427.22,1256.82 4569.17,1114.87 4569.17,1096.28 4580.55,1084.9 4614.61,1084.9 4647.95,1051.56 4647.95,1036.76 4706.97,977.74 4847.67,977.74 4979.44,845.97 5058.54,845.97 5119.51,785 5222.77,785 v1(5248.23,759.55)
AM263P_ICSSM_MII1_RXD1: U1.G16 U50.40 | length 1530.8
  Top Layer w5.3: v1(5208.86,759.55) 5208.86,785.31 5228.54,805 U50.40@5228.54,846.81
  Top Layer w10: U1.G16@4019.57,1193.82 v1(4035.32,1209.57)
  SIG 1 w4.75: v1(4035.32,1209.57) 4270.86,1209.57 4296.38,1235.08 4434.74,1235.08 4474.51,1195.31 4474.51,1140.59 4647.41,967.69 4843.5,967.69 4975.28,835.92 5054.38,835.92 5130.76,759.55 v1(5208.86,759.55)
AM263P_ICSSM_MII1_RXD2: U1.E17 U50.37 | length 1529.3
  Top Layer w4: U1.E17@4051.07,1256.81 4066.82,1272.56 4101.95,1272.56 4113.62,1284.23 4114.06,1284.23
  Top Layer w5.3: 4114.06,1284.23 4197.31,1284.23 4210.63,1297.55 4250.64,1297.55 4270.36,1317.28 4450.47,1317.28 4460,1307.75 v1(4460,1271.09) ; v1(5131.77,882.24) U50.37@5173.43,882.24
  SIG 1 w4.75: v1(4460,1271.09) 4461.55,1269.54 4471.38,1269.54 4690.23,1050.69 4690.23,1036.35 4728.73,997.84 4860.42,997.84 4990.73,867.53 5070.26,867.53 5127.8,810 5158.56,810 5167.94,819.38 5167.94,876.31 5154.35,889.89 5141.18,889.89 5133.53,882.24 v1(5131.77,882.24)
AM263P_ICSSM_MII1_RXD3: U1.E18 U50.35 | length 1525.8
  Top Layer w4: U1.E18@4082.57,1256.81 4104.96,1256.81
  Top Layer w5.3: 4104.96,1256.81 4121.72,1273.58 4202.45,1273.58 4215.82,1286.95 4255.03,1286.95 4270.57,1302.49 4414.23,1302.49 4421.61,1295.1 v1(4423.69,1295.1) ; v1(5131.77,921.61) U50.35@5173.43,921.61
  SIG 1 w4.75: v1(4423.69,1295.1) 4463.21,1295.1 4702.13,1056.19 4702.13,1038.66 4732.9,1007.89 4864.58,1007.89 4970.98,901.49 5157.7,901.49 5180,879.19 5180,854.78 5182.78,851.99 5211.08,851.99 5213.86,854.78 5213.86,875 5167.25,921.61 v1(5131.77,921.61)
AM263P_ICSSM_MII1_RXDV: U1.F16 U50.33 | length 1526.7
  Top Layer w5.3: v1(5131.16,960.98) U50.33@5173.43,960.98
  Top Layer w10: U1.F16@4019.57,1225.32 v1(4035.32,1241.06)
  SIG 1 w4.75: v1(4035.32,1241.06) 4041.58,1234.81 4166.03,1234.81 4180,1248.78 4180,1259.38 4193.93,1273.3 4265,1273.3 4285.64,1293.95 4384.05,1293.95 4404.45,1314.35 4462.72,1314.35 4716.57,1060.5 4716.57,1038.43 4737.06,1017.94 4979.18,1017.94 5016.02,981.1 5142.47,981.1 5150.41,989.04 5150.41,1010.7 5159.71,1020 5173.32,1020 5177.73,1015.59 5177.73,969.09 5169.62,960.98 v1(5131.16,960.98)
AM263P_ICSSM_MII1_RXER: R111.1 R123.2 R229.2 U1.F15 U22.46 | length 3812.4
  Top Layer w5.3: v1(6695,890) 6740,890 6751.09,901.09 6789.71,901.09 6795,906.38 6795,924.79 R111.1@6796.28,926.06 R123.2@6848,926.06 v1(6848,888.56)
  Top Layer w10: U1.F15@3988.08,1225.32 v1(4003.83,1241.06)
  SIG 1 w4.75: v1(4003.83,1241.06) 4019.95,1224.94 4048.81,1224.94 4051.93,1221.82 4248.36,1221.82 4302.6,1276.07 4415.5,1276.07 4415.71,1275.85 4422.39,1275.85 4461.67,1236.58 4483.31,1236.58 4607.66,1112.23 ; 4607.66,1112.2 4674.65,1045.21 4674.65,1037.26 4724.12,987.79 4851.83,987.79 4983.6,856.02 5062.71,856.02 5120.89,797.83 5237.16,797.83 5283.33,751.67 5283.33,738.42 5323.62,698.12 5627.08,698.12 5636.41,688.8 5692.35,688.8 5692.41,688.86 5708.36,688.86 5708.42,688.8 5748.94,688.8 5813.88,623.85 5944.6,623.85 5951.6,630.85 6011.1,630.85 6104.93,537.03 6131.2,510.75 6222.36,510.75 6229.94,518.33 6398.53,518.33 6423.2,543 6568.25,543 6619.77,594.53 6777.57,594.53 6848,664.96 v1(6848,888.56)
  Bottom Layer w5.3: U22.46@6694.07,853.9 6694.07,889.07 v1(6695,890) ; R229.2@6846.59,927.98 6846.59,889.97 v1(6848,888.56)
AM263P_ICSSM_MII1_RXLINK: R110.1 R122.2 R227.2 U1.D18 U22.47 | length 4682.2
  Top Layer w5.3: U1.D18@4082.57,1288.31 4100.01,1288.31 4109.25,1297.55 4114.06,1297.55 4175.56,1297.55 4184.2,1306.2 4184.2,1360.45 4202.39,1378.64 4347.13,1378.64 4354.07,1371.7 4387.81,1371.7 4423.28,1407.16 4423.28,1708.76 4471.69,1757.18 4813.15,1757.18 4854.07,1798.09 5119.88,1798.09 5145.13,1772.84 5250.58,1772.84 5334.04,1856.3 5534.57,1856.3 5622.67,1944.4 6576.79,1944.4 6627.71,1995.33 6632.86,1995.33 6697.54,2060 v1(6810,2060) ; R110.1@6729.39,926.46 v1(6755,926.46)
  SIG 1 w4.75: v1(6810,2060) 6803.55,2053.55 6803.55,1979.56 6815.53,1967.58 6815.53,1930 6802.89,1917.36 6802.89,1868.09 6839.95,1831.03 6839.95,1375.84 6846.59,1369.2 v1(6846.59,1065.8)
  Bottom Layer w5.3: U22.47@6713.76,853.9 6713.76,879.37 6729.39,895 R122.2@6729.39,926.46 v1(6755,926.46) 6785,956.46 6785,987.75 6762.73,1010.01 R227.2@6762.73,1065.31 6846.11,1065.31 v1(6846.59,1065.8)
AM263P_ICSSM_MII1_TXCLK: R86.1 U50.18 | length 1596.1
  Top Layer w5.3: R86.1@4111,1632.17 v1(4111,1660.23) ; v1(5248.23,1280.53) 5267.91,1260.84 U50.18@5267.91,1193.26
  SIG 1 w4.75: v1(4111,1660.23) 4111.4,1659.82 4111.4,1648.85 4279.65,1480.6 4399.37,1480.6 4484.34,1395.64 4525.74,1395.64 4555,1366.38 4555,1312.77 4705.46,1162.31 4741.59,1162.31 4777.03,1126.87 4800.47,1126.87 4883.5,1209.9 5081.16,1209.9 5096.79,1194.27 5161.97,1194.27 v1(5248.23,1280.53)
AM263P_ICSSM_MII1_TXCLK_R: R86.2 U1.C16 | length 308.1
  Top Layer w4: v1(4110.55,1554.46) 4110.55,1583.95 R86.2@4110.9,1584.29
  Top Layer w10: U1.C16@4019.57,1319.8 v1(4035.32,1335.55)
  SIG 1 w4: v1(4035.32,1335.55) 4035.32,1414.29
  SIG 1 w4.75: 4035.32,1414.29 4035.32,1489.06 4098.14,1551.88 4104.38,1551.88 4106.97,1554.46 v1(4110.55,1554.46)
AM263P_ICSSM_MII1_TXD0: R81.1 U50.28 | length 1656.7
  Top Layer w4.75: R81.1@4330.08,1492.68 4354.68,1492.68 4357.46,1489.9 4357.46,1453.29 v1(4360,1450.76)
  Top Layer w5.3: v1(5086.77,1039.72) 5087.15,1040.1 5103.84,1040.1 5123.15,1059.41 U50.28@5173.43,1059.41
  SIG 1 w4.75: v1(4360,1450.76) 4164.17,1450.76 4150.83,1437.42 4150.83,1389.74 4166.32,1374.25 4185.04,1374.25 4193.93,1383.14 4193.93,1400.93 4197.49,1404.49 4214.45,1404.49 4217.23,1401.71 4217.23,1381.95 4224.93,1374.25 4288.08,1374.25 4297.32,1365 4297.32,1346.11 4294.33,1343.12 4267.78,1343.12 4265,1340.34 4265,1322.85 4273.8,1314.05 4375.72,1314.05 4396.13,1334.45 4471.04,1334.45 4728.5,1077 4779.38,1077 4807.3,1049.09 5077.41,1049.09 v1(5086.77,1039.72)
AM263P_ICSSM_MII1_TXD0_R: R81.2 U1.B18 | length 267.7
  Top Layer w5.3: U1.B18@4082.57,1351.3 4108.55,1377.29 4137.9,1377.29 4176.16,1415.55 4176.16,1430.7 4209.92,1464.46 4237.54,1464.46 4257.59,1484.51 4274.67,1484.51 R81.2@4282.84,1492.68
AM263P_ICSSM_MII1_TXD1: R82.1 U50.26 | length 1655.1
  Top Layer w4.75: v1(4179.19,1508.25) 4179.19,1531.6 4190.82,1543.23 R82.1@4212.87,1543.23
  Top Layer w5.3: v1(5086.77,1079.09) 5104.16,1079.09 5123.85,1098.78 U50.26@5173.43,1098.78
  SIG 1 w4.75: v1(4179.19,1508.25) 4176.84,1508.25 4169.78,1501.19 4077.69,1501.19 4074.9,1498.41 4074.9,1465.84 4079.64,1461.1 4124.01,1461.1 4124.14,1460.97 4283.08,1460.97 4292.39,1470.28 4383.28,1470.28 4701.77,1151.79 4737.89,1151.79 4772.86,1116.82 4810,1116.82 4890.95,1197.77 5074.44,1197.77 5127.21,1145.01 5127.21,1094.1 5112.19,1079.09 v1(5086.77,1079.09)
AM263P_ICSSM_MII1_TXD1_R: R82.2 U1.B17 | length 269.2
  Top Layer w4: U1.B17@4051.07,1351.3 4068.69,1368.92 4068.69,1414.29
  Top Layer w5.3: 4068.69,1414.29 4068.69,1446.09 4095.14,1472.55 4127.82,1472.55 4138.16,1482.89 4203.71,1482.89 4212.87,1492.05 R82.2@4212.87,1495.98
AM263P_ICSSM_MII1_TXD2: R83.1 U50.24 | length 1511
  Top Layer w4.75: R83.1@4324.87,1353.13 4348.14,1353.13 4354.85,1346.42 v1@4357.02,1346.42
  Top Layer w5.3: v1(5086.77,1118.46) 5110.31,1118.46 5130,1138.15 U50.24@5173.43,1138.15
  SIG 1 w4.75: v1(4357.55,1346.15) 4343.27,1360.42 4335.8,1360.42 4325.24,1349.87 4325.24,1337.5 4338.64,1324.1 4364.69,1324.1 4383.16,1342.57 4383.16,1365.86 4387.84,1370.54 4399.37,1370.54 4407.78,1362.14 4407.78,1350 4413.15,1344.63 4423.05,1344.63 4428.41,1349.98 4428.41,1367.11 4431.84,1370.54 4449.17,1370.54 4729.02,1090.69 4783.55,1090.69 4815.1,1059.14 4826.97,1059.14 4829.75,1061.92 4829.75,1090.18 4836.29,1096.72 4847.67,1096.72 4855.63,1088.76 4855.63,1062.14 4858.63,1059.14 4960.56,1059.14 4963.34,1061.92 4963.34,1075.99 4960.56,1078.78 4888.64,1078.78 4882.39,1085.02 4882.39,1108.3 4909.09,1135 4923.24,1135 4935.59,1122.65 4935.59,1111.61 4947.57,1099.63 4966,1099.63 4976.85,1110.49 4976.85,1127.67 4984.19,1135 5019.14,1135 5031.47,1122.67 5031.47,1105.62 5034.26,1102.84 5045.64,1102.84 5050.6,1107.8 5050.6,1115.68 5053.38,1118.46 v1(5086.77,1118.46)
AM263P_ICSSM_MII1_TXD2_R: R83.2 U1.D16 | length 396.3
  Top Layer w4.75: v1@4206.88,1351.06 4208.96,1348.98 4215.3,1348.98 4217.39,1351.06 4275.55,1351.06 R83.2@4277.62,1353.13
  Top Layer w10: U1.D16@4019.57,1288.31 v1(4035.32,1304.06)
  SIG 1 w4.75: v1(4035.32,1304.06) 4089.18,1304.06 4093.43,1308.3 4093.43,1330.34 4087,1336.78 4063.44,1336.78 4059.87,1340.35 4059.87,1351.72 4064.35,1356.2 4125.54,1356.2 4152.86,1328.88 4191.63,1328.88 v1(4209.18,1346.44)
AM263P_ICSSM_MII1_TXD3: R84.1 U50.22 | length 1628.6
  Top Layer w4.75: R84.1@4324.87,1445.88 4324.87,1415.2 4327.65,1412.42 v1(4370.94,1412.42)
  Top Layer w5.3: v1(5086.77,1157.83) 5065.63,1157.83 5060,1163.46 5060,1212.97 5066.68,1219.65 5083.67,1219.65 5086.77,1216.55 5086.77,1186.62 5094.7,1178.69 5102.75,1178.69 5108.69,1184.63 5108.69,1219.52 5115,1225.83 5160.62,1225.83 5169.97,1216.48 5169.97,1205.57 5166.86,1202.46 5131.69,1202.46 5128.59,1199.36 5128.59,1180.62 5131.69,1177.52 U50.22@5173.43,1177.52
  SIG 1 w4.75: v1(4370.94,1412.42) 4349.29,1434.07 4293.37,1434.07 4288.21,1428.91 4288.21,1393.36 4299.62,1381.95 4457.4,1381.95 4697.6,1141.74 4733.73,1141.74 4768.7,1106.77 4866.65,1106.77 4912.39,1152.51 4912.39,1165.47 4916.79,1169.87 4928.94,1169.87 4932.42,1166.39 4932.42,1152.63 4938.17,1146.88 4956.11,1146.88 4963.82,1154.59 4963.82,1163.61 4966.6,1166.39 4982.22,1166.39 4985,1163.61 4985,1150.05 4990,1145.05 5010,1145.05 5014.57,1149.62 5014.57,1160.66 5017.36,1163.44 5037.22,1163.44 5040,1160.66 5040,1150.05 5045,1145.05 5073.99,1145.05 v1(5086.77,1157.83)
AM263P_ICSSM_MII1_TXD3_R: R84.2 U1.C17 | length 293.3
  Top Layer w5.3: U1.C17@4051.07,1319.8 4068.04,1336.78 4088.58,1336.78 4118.11,1366.3 4141.9,1366.3 4186.76,1411.16 4186.76,1426.31 4213.15,1452.7 4249.44,1452.7 4256.26,1445.88 R84.2@4277.62,1445.88
AM263P_ICSSM_MII1_TXEN: R85.1 U50.20 | length 1683.4
  Top Layer w4.75: v1(4149,1660.23) 4159.49,1649.74 R85.1@4159.49,1607.02
  Top Layer w5.3: v1(5208.86,1290.74) 5208.86,1264.69 5228.54,1245 U50.20@5228.54,1193.26
  SIG 1 w4.75: v1(4149,1660.23) 4209.95,1599.28 4209.95,1598.74 4318.04,1490.65 4407.8,1490.65 4492.77,1405.69 4529.9,1405.69 4565.05,1370.54 4565.05,1316.93 4709.62,1172.36 4826.74,1172.36 4874.33,1219.95 5085.33,1219.95 5095.23,1210.05 5111.68,1210.05 5116.23,1214.6 5116.23,1289.96 5119.01,1292.74 5152.1,1292.74 5154.88,1289.96 5154.88,1221.62 5161.5,1215 5168.49,1215 5208.86,1255.37 v1(5208.86,1290.74)
AM263P_ICSSM_MII1_TXEN_R: R85.2 U1.A17 | length 240.8
  Top Layer w5.3: U1.A17@4051.07,1382.8 4051.07,1414.29 4051.07,1444.18 4090.03,1483.15 4122.33,1483.15 4159.49,1520.3 R85.2@4159.49,1559.77
AM263P_IEP0_EDC_SYNC_OUT0: J6/J8.72 R88.1 | length 862.6
  Bottom Layer w5.3: R88.1@4098.66,1812.24 4147.24,1812.24 4181.13,1846.13 4406.25,1846.13 4420.63,1860.51 4814.68,1860.51 J6/J8.72@4904.17,1950
AM263P_IEP0_EDC_SYNC_OUT0_R: R88.2 U1.D15 | length 565.1
  Top Layer w10: U1.D15@3988.08,1288.31 v1(4003.83,1304.06)
  SIG 1 w4: v1(4003.83,1304.06) 4018.83,1319.06 4018.83,1414.29
  SIG 1 w4.75: 4018.83,1414.29 v1(4018.83,1791.62)
  Bottom Layer w5.3: v1(4018.83,1791.62) 4039.45,1812.24 R88.2@4059.29,1812.24
AM263P_IEP0_EDIO_DATA_IN_OUT31: J6/J8.71 R87.1 | length 980.4
  Bottom Layer w5.3: R87.1@4098.66,1769.24 4119.24,1769.24 4185.53,1835.53 4410.64,1835.53 4424.63,1849.52 4903.7,1849.52 J6/J8.71@5004.17,1950
AM263P_IEP0_EDIO_DATA_IN_OUT31_R: R87.2 U1.C15 | length 621.7
  Top Layer w10: U1.C15@3988.08,1319.8 v1(4003.83,1335.55)
  SIG 1 w4: v1(4003.83,1335.55) 4003.83,1414.29
  SIG 1 w4.75: v1(3999.3,1825.38) 3999.58,1825.11 3999.58,1783.65 4003.83,1779.4 4003.83,1414.29
  Bottom Layer w5.3: v1(3999.3,1825.38) 3999.3,1783.54 4013.6,1769.24 R87.2@4059.29,1769.24
AM263P_INT1_PB_GPIO123: U1.D14 U34.4 | length 4450
  Top Layer w5.3: v1(635.66,2123.71) 643.9,2115.47 U34.4@651.22,2115.47 ; v1(3750,1830) 3827.92,1830 3869.54,1871.62 3930.98,1871.62 3938.17,1864.43 v1(4003.05,1864.43)
  Top Layer w10: U1.D14@3956.58,1288.31 v1(3972.33,1304.06)
  SIG 1 w4: v1(3972.33,1304.06) 3988.83,1320.55 3988.83,1414.29
  SIG 1 w4.75: v1(635.66,2123.71) 645.95,2134 741.21,2134 768.33,2106.89 768.33,2036.68 782,2023 ; 782.08,2023.08 793.15,2012.84 821.4,1984.59 893.41,1984.59 923,1955 970,1955 1063.74,2048.74 1270.43,2048.74 1344.17,1975 1424.99,1975 1438.27,1961.73 1438.27,1952.73 1466.13,1924.87 1563.87,1924.87 1605.23,1883.5 1676.77,1883.5 1748.63,1811.63 1867.13,1811.63 1900,1778.77 2246.64,1778.77 2319.87,1851.99 2525.34,1851.99 2538.28,1864.94 2590.04,1916.69 2590.04,1920.49 cw(c2594.79,1920.49) 2590.04,1920.68 2590.05,1920.87 2590.36,1928.38 2653.29,1991.32 2720.32,1991.32 2732.05,1979.58 2835.23,1978.96 2863.05,1951.13 2865.02,1951.13 2868.48,1951.13 ccw(c2873.05,1969.83) 2873.52,1950.59 2895.81,1951.13 2899.74,1951.13 2901.14,1949.74 2946.35,1904.53 3106.89,1904.53 3129.43,1881.99 3386.15,1881.99 3386.67,1882.51 3697.49,1882.51 v1(3750,1830) ; 3988.83,1414.29 3988.83,1547.33 3993.66,1552.16 3993.66,1775.35 3980.05,1788.96 3980.05,1841.43 v1(4003.05,1864.43)
AM263P_LED_DRIVER_EN: R278.2 U48.8 U63.5 | length 3351.5
  Top Layer w5.3: U48.8@2117.28,1795 2161.53,1795 2185.53,1819 R278.2@2185.53,1859.15 2147.08,1859.15 2140.23,1866 2114.88,1866 2095.82,1846.93 2095.82,1835.67 2034.1,1773.94 2034.1,1627.67 2044.32,1617.45 2044.32,1526.08 2025.08,1506.84 2025.08,1486.83 2088.76,1423.14 2141.75,1423.14 2171.95,1392.93 2171.95,1389.98 2200.51,1361.42 2238.3,1361.42 v1(2248.87,1350.85)
  SIG 1 w4.75: v1(2248.87,1350.85) 2309.54,1350.85 2387.71,1429.01 2439.88,1429.01 2457.52,1411.37 2457.52,1251.27 2337.7,1131.45 2337.7,939.98 2328.92,931.2 2294.31,931.2 2166.65,1058.86 2037.46,1058.86 1991.12,1012.52 1991.12,970.66 2066.47,895.31 2066.47,757.91 2122.22,702.17 2359.29,702.17 2406.84,654.62 2453.41,654.62 2536.75,737.96 2565.91,737.96 2579.67,724.21 2579.67,722.21 2592.72,709.16 2612.01,709.16 2612.29,709.44 2646.62,709.44 2657.89,720.72 2657.89,758.14 2638.35,777.68 2624.47,777.68 v1(2623.53,778.61)
  Bottom Layer w5.3: U63.5@2578.49,658.28 2578.49,685.5 2565.51,698.48 2547.79,698.48 2539.12,707.15 2539.12,739.76 2577.98,778.61 v1(2623.53,778.61)
AM263P_LED_EN: R303.1 R304.2 U63.6 | length 1068.4
  Top Layer w5.3: R303.1@2617.63,186.73 2559.79,186.73 R304.2@2558.18,185.12 2558.18,236.62 2610.52,288.95 2646.74,288.95 2724.79,367 2724.79,420.38 2749.79,445.37 2790.99,445.37 2794.1,448.48 2794.1,519.21 2857.2,582.31 2857.2,620.33 2829.89,647.63 2711.09,647.63 2700.52,658.2 2700.52,685.13 2709.7,694.32 2709.7,721.25 2698.27,732.69 2646.08,732.69 2642.08,728.69 v1(2638.64,728.69)
  Bottom Layer w5.3: U63.6@2598.18,658.28 2598.18,688.22 v1(2638.64,728.69)
AM263P_LIN1_RXD: U1.A9 U52.33 | length 1958.3
  Top Layer w4: 3797.83,1414.29 3797.83,1384.07 U1.A9@3799.1,1382.8
  Top Layer w5.3: 3797.83,1414.29 3797.83,1483.15 3853.82,1539.13 3853.82,1561.66 3839.11,1576.37 3839.11,1691.5 v1(3821.76,1708.85) ; v1(4408.39,591.26) 4428.07,610.95 U52.33@4500.04,610.94
  Bottom Layer w5.3: v1(3821.76,1708.85) 3818.33,1708.85 3798.35,1688.87 3798.35,1643.66 3831.28,1610.73 3909.32,1610.73 4055,1465.05 4055,1388.67 4095.15,1348.52 4095.15,874.56 4194.89,774.82 4289.15,774.82 4352.47,711.5 4352.47,625.82 4387.04,591.26 v1(4408.39,591.26)
AM263P_LIN1_TXD: R297.1 U52.31 | length 1530.9
  Top Layer w5.3: R297.1@3817.25,1638.93 3817.85,1655.39 3817.98,1655.52 v1(3817.98,1673.05) ; v1(4408.39,630.63) 4428.07,650.32 U52.31@4500.04,650.32
  Bottom Layer w5.3: v1(3817.98,1673.05) 3820.01,1636.99 3834.85,1622.15 3912.89,1622.15 4070,1465.04 4070,1395 4104.45,1360.55 4104.45,880.25 4199.2,785.5 4304.49,785.5 4355.15,734.84 4360.28,734.84 4391.61,703.52 4391.61,646.83 4407.81,630.63 v1(4408.39,630.63)
AM263P_LIN1_TXD_R: R297.2 U1.B9 | length 264.9
  Top Layer w4: 3783.35,1414.29 3783.35,1367.05 U1.B9@3799.1,1351.3
  Top Layer w5.3: 3783.35,1414.29 3783.35,1418.8 3786.5,1421.94 3786.5,1492.41 3809.52,1515.44 3809.52,1553.6 3817.25,1561.33 R297.2@3817.25,1595.63
AM263P_LIN2_RXD: U1.B8 U52.41 | length 3572.7
  Top Layer w4: 3751.86,1380 3751.86,1367.05 U1.B8@3767.61,1351.3
  Top Layer w5.3: 3751.86,1380 3751.86,1422.06 3736.85,1437.07 3736.85,1474.86 3743.45,1481.47 3743.45,1565.9 3743.22,1566.14 3743.22,1677.47 v1(3807.77,1742.02) ; U52.41@4574.84,496.77 4574.84,451.2 4585.49,440.55 v1(4585.49,440)
  Bottom Layer w5.3: v1(3807.77,1742.02) 3822.23,1742.02 3851.42,1712.83 3851.42,1694.31 3839.11,1682 3839.11,1645.82 3850.65,1634.28 3915.75,1634.28 3965.77,1584.26 4150.61,1584.26 4238.54,1496.32 4509.56,1496.32 4555.91,1542.67 4619.9,1542.67 4633.91,1556.68 4633.91,1565.54 4698.62,1630.25 4975.47,1630.25 5003.34,1602.38 5003.34,1593.17 5135.82,1460.69 5135.82,1127.43 5151.3,1111.96 5151.3,874.15 5125,847.86 5125,769.32 5051.62,695.93 5051.62,597.78 4877.46,423.62 4601.87,423.62 v1(4585.49,440)
AM263P_LIN2_RXD_PR0_PRU0_GPIO11: J5/J7.43 U52.2 | length 638.1
  Top Layer w5.3: U52.2@4629.96,532.2 4691.22,532.2 4705,518.43 4705,490.59 v1(4705.59,490)
  Bottom Layer w5.3: J5/J7.43@4304.17,250 4355,300.83 4418.22,300.83 4457.78,340.39 4457.78,387.87 4559.9,490 v1(4705.59,490)
AM263P_LIN2_TXD: R166.1 U52.39 | length 1782.1
  Top Layer w5.3: R166.1@3769.66,1642.44 3769.66,1665.2 v1(3778.82,1674.36) ; v1(4444.77,448.84) 4445.11,448.5 4519.71,448.5 4535.47,464.27 U52.39@4535.47,496.77
  Bottom Layer w5.3: v1(3778.82,1674.36) 3778.85,1661.78 3778.85,1657.39 3776.22,1654.76 3773,1651.53 3773,1638 3817.25,1593.75 3822.43,1588.57 3916.48,1588.57 3918.04,1587.02 4040,1465.06 4040,1388.66 4085.85,1342.81 4085.85,868.87 4195.74,758.98 4290,758.98 4341.87,707.11 4341.87,621.43 4354.64,608.66 4354.64,538.97 v1(4444.77,448.84)
AM263P_LIN2_TXD_PR0_PRU0_GPIO9: J5/J7.44 U52.3 | length 666.9
  Top Layer w5.3: U52.3@4629.96,551.89 4700.67,551.89 4742.56,510 v1(4742.56,490.87)
  Bottom Layer w5.3: J5/J7.44@4404.17,250 4449.17,295 4535.31,295 4558.86,318.54 4558.86,454.51 4572.72,468.37 4720.06,468.37 v1(4742.56,490.87)
AM263P_LIN2_TXD_R: R166.2 U1.A8 | length 218.4
  Top Layer w4: U1.A8@3767.61,1382.8 3767.61,1414.29
  Top Layer w5.3: 3767.61,1414.29 3767.61,1418.04 3775.9,1426.33 3775.9,1481.99 3769.66,1488.22 R166.2@3769.66,1595.2
AM263P_MCAN3_RX: R249.1 U1.B7 | length 6218.3
  Top Layer w4: 3718.3,1414.47 3718.54,1414.23 3718.54,1369.1 U1.B7@3736.16,1351.48
  Top Layer w5.3: v1(3710,1820.18) 3710.05,1820.13 3710.05,1748.76 3729.52,1729.29 3729.52,1724.38 3729.57,1724.32 3729.57,1693.81 3721.77,1686.01 3721.77,1569.08 3721.56,1568.87 3721.56,1527.25 3710.06,1515.75 3710.06,1422.71 3718.3,1414.47
  SIG 1 w4.75: v1(5738.52,2097.5) 5831.21,2097.5 5903.56,2169.85 6604.05,2169.85 6643.91,2129.99 6756.07,2129.99 6777.03,2109.04 6777.03,1951.63 6789.52,1939.14 6789.52,1335.16 6789.52,1246.1 6743.49,1200.06 6743.49,1110.67 6815.53,1038.63 6815.53,984.47 6964.3,835.7 6964.3,390.66 7054.96,300 7185.73,300 7238.93,246.79 7238.93,147.52 v1(7250,136.46)
  Bottom Layer w5.3: v1(3710,1820.18) 3710.6,1820.18 3722.29,1808.49 3838.74,1808.49 3877.8,1847.55 3918.43,1847.55 3974.4,1791.58 3974.4,1766.76 4002.88,1738.28 4123.15,1738.28 4199.21,1814.33 4419.42,1814.33 4430.26,1825.18 5015.92,1825.18 5177.59,1986.84 5627.87,1986.84 v1(5738.52,2097.5) ; R249.1@7219.69,61.46 7219.69,79.68 7250,110 v1(7250,136.46)
AM263P_MCAN3_TX: R401.1 U42.1 | length 5733.5
  Top Layer w5.3: R401.1@3678.01,1749.69 R401.1@3679.98,1751.65 ; R401.1@3678.01,1753.62 3678.01,1830.11 3697.42,1849.52 3807.81,1849.52 3859.79,1901.5 4063.15,1901.5 4067.23,1905.58 4427.03,1905.58 4448.86,1927.4 4448.86,2105.88 4442.21,2112.53 v1(4442.21,2167.19)
  SIG 1 w4.75: 5200,2146.14 5552.02,2146.14 5647.16,2051 5844,2051 5899.97,2106.97 6620.38,2106.97 6750,1977.35 6750,1964.45 6779.47,1934.98 6779.47,1330.99 6779.47,1250.26 6733.44,1204.22 6733.44,1101.56 6777.03,1057.97 6777.03,1001.63 6954.25,824.41 6954.25,370.75 7086.18,238.82 v1(7219.69,238.82)
  SIG 1 w5.3: v1(4442.21,2167.19) 5178.95,2167.19 5200,2146.14
  Bottom Layer w5.3: U42.1@7127.91,174.84 7148.62,174.84 7169.59,195.81 7176.68,195.81 v1(7219.69,238.82)
AM263P_MCAN5_RX: U1.G4 U52.37 | length 3363.9
  Top Layer w5.3: v1(4248.9,552.05) 4249.56,552.05 4270.75,573.23 4277.33,573.23 4307.29,603.19 4353.85,603.19 4424.84,532.2 U52.37@4500.04,532.2
  Top Layer w10: v1(3625.87,1209.57) U1.G4@3641.62,1193.82
  SIG 1 w4: 3515.64,1230.74 3548.57,1230.74 3553.24,1226.06 3609.38,1226.06 v1(3625.87,1209.57)
  SIG 1 w5.3: v1(2908.1,1252.01) v1@2911.51,1252.01 ; v1@2911.51,1253.55 2920.61,1262.64 3031.75,1262.64 3042.39,1252.01 3153.29,1252.01 3174.56,1230.74 3515.64,1230.74
  Bottom Layer w5.3: v1(2908.1,1252.01) 2928.54,1231.57 2928.54,1133.26 2981.03,1080.77 2981.03,1069.89 3059.43,991.49 3059.43,950.66 3042.1,933.34 3042.1,839.53 2926.28,723.72 2926.28,636.68 2926.34,636.62 2926.34,620.07 2995.76,550.66 3341.03,550.66 3408.32,483.36 3408.32,427.64 3433.18,402.78 3499.55,402.78 3519.26,383.08 3780.43,383.08 3808.5,355 3933.54,355 4058.4,479.86 4174.91,479.86 4247.09,552.05 v1(4248.9,552.05)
